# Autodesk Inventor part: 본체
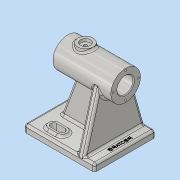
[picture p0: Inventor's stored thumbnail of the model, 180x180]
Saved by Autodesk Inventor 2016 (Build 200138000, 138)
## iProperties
Created: 2019-10
Part Number: 본체
Material: 알루미늄 6061
Document SubType Name: Modeling
Designer: MIRAE
Density: 2.7 g/cm^3
Appearance: 알루미늄 - 평지
Mass: 584.809 g
Surface Area: 539.314 cm^2
Volume: 216.596 cm^3
Author: MIRAE
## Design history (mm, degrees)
sketch "스케치1"
  geometry: L1 (-41, 0)-(41, 0); L2 (-41, 0)-(-41, 21); L3 (-41, 21)-(41, 21); L4 (41, 21)-(41, 0); 2 further points
  constraints: 8 end point, 2 midpoint, 2 perpendicular, 1 horizontal, 1 vertical, 1 vertical alignment
  dimensions: "d0" = 42 diameter of L3 L1; "d1" = 82 distance between parallel lines of L4 L2
revolve "회전1" sketch "스케치1" stored, may be unused: angle "d2" = 90 deg
sketch "스케치2"
  geometry: L1 (41, 21)-(41, -21) reference; L2 (41, 0)-(-41, 0); L3 (-41, 21)-(-41, -21) reference; L4 (41, 0)-(41, 14.5); L5 (41, 14.5)-(-21, 14.5); L6 (-21, 14.5)-(-21, 11.5); L7 (-21, 11.5)-(-41, 11.5); L8 (-41, 11.5)-(-41, 0); 1 further point
  constraints: 12 end point, 2 midpoint, 2 perpendicular, 2 point on line, 1 collinear, 1 horizontal
  dimensions: "d3" = 29 diameter of L5 L2; "d4" = 23 diameter of L7 L2; "d5" = 62 distance of L4.end L5.end
revolve "회전2" sketch "스케치2" stored, may be unused: angle "d6" = 90 deg
node "작업 평면1"
sketch "스케치3"
  geometry: L1 (-60, 43)-(40, 43); L2 (40, 43)-(40, -43); L3 (40, -43)-(-60, -43); L4 (-60, -43)-(-60, 43); 2 further points
  constraints: 8 end point, 2 parallel, 1 horizontal, 1 horizontal alignment, 1 midpoint, 1 perpendicular
  dimensions: "d87" = 100 distance of L2.end L3.end; "d88" = 86 distance of L1.end L2.end; "d89" = 40 distance from line of L2 point (0, 0)
extrude "돌출1" join sketch "스케치3" distance "d10" = 10; taper "d11" = 0 deg
node "작업 평면2"
node "작업 평면3"
sketch "스케치7"
  geometry: L1 (-41, -21)-(-41, 21) reference; C1 r 11 at (-16, 0); 1 further point
  constraints: 1 centre point, 1 horizontal alignment
  dimensions: "d24" = 22 diameter of C1; "d25" = 25 distance from line of L1 C1.centre
extrude "돌출3" join sketch "스케치7" stored distance "d26" = 10; taper "d27" = 0 deg
sketch "스케치8"
  geometry: L1 (-34, 27)-(-22, 27); L2 (-34, 20)-(-22, 20); L3 (-22, 34)-(-34, 34); L4 (-60, 43)-(-60, -43) reference; A1 r 7 centre (-34, 27) between (-34, 34) and (-34, 20); A2 r 7 centre (-22, 27) between (-22, 20) and (-22, 34); 2 further points
  constraints: 8 end point, 4 point on circle, 4 tangent, 2 centre point, 1 horizontal, 1 midpoint, 1 parallel
  dimensions: "d28" = 12 distance of L1.start L1.end; "d31" = 14 distance between parallel lines of L2 L3; "d32" = 27 vertical distance of point (0, 0) L1.end; "d90" = 26 distance from line of L4 L1.start
extrude "돌출4" join sketch "스케치8" distance "d33" = 3; taper "d34" = 0 deg
sketch "스케치9"
  geometry: L1 (-34, 27)-(-22, 27); L2 (-34, 22.5)-(-22, 22.5); L3 (-22, 31.5)-(-34, 31.5); A1 r 4.5 centre (-34, 27) between (-34, 31.5) and (-34, 22.5); A2 r 4.5 centre (-22, 27) between (-22, 22.5) and (-22, 31.5); A3 r 7 centre (-22, 27) between (-22, 20) and (-22, 34) reference; 2 further points
  constraints: 8 end point, 4 point on circle, 4 tangent, 2 centre point, 1 concentric, 1 horizontal, 1 midpoint, 1 parallel
  dimensions: "d35" = 9 distance between parallel lines of L2 L3; "d36" = 12 distance of L1.start L1.end
extrude "돌출5" cut sketch "스케치9" stored distance "d37" = 3; taper "d38" = 0 deg
hole "구멍1" diameter "d41" = 4.917; stored, may be unused: countersink angle "d45" = 90 deg, drill point angle "d47" = 118 deg; dims "d39" = 10, "d40" = 10, "d42" = 12, "d43" = 14, "d44" = 4, "d46" = 17.1
sketch "스케치10"
  geometry: 2 further points
  constraints: 1 horizontal alignment
  dimensions: "d48" = 18 distance of point (0, 0) point (-18, 0)
hole "구멍2" sketch "스케치10" at (-18, 0) diameter "d49" = 2.459; stored, may be unused: countersink angle "d53" = 90 deg, drill point angle "d55" = 118 deg; dims "d50" = 8, "d51" = 14, "d52" = 4, "d54" = 10
node "작업 평면4"
fillet "모깎기4" dims "d77" = 3
chamfer "모따기1" distance "d78" = 1; stored, may be unused: second distance "d79" = 2, angle "d80" = 45 deg
fillet "모깎기5" dims "d91" = 3
fillet "모깎기6" dims "d92" = 3
node "작업 평면5"
sketch "스케치16"
  geometry: L1 (-42.889, -78.191)-(-21, 0); L2 (-21, 0)-(21, 0); L3 (0, 0)-(0, -86); L4 (-40, -86)-(40, -86) reference; L5 (42.889, -78.191)-(21, 0); A1 r 3 centre (-40, -79) between (-40, -76) and (-43, -79) reference; A2 r 3 centre (40, -79) between (43, -79) and (40, -76); A3 r 21 centre (0, 0) between (-21, 0) and (21, 0); 1 further point
  constraints: 8 end point, 6 point on circle, 5 symmetric about line, 2 centre point, 2 midpoint, 1 coincident, 1 horizontal, 1 horizontal alignment, 1 tangent, 2 other
feature "리브4" sketch "스케치16" dims "d94" = 1, "d95" = 10, "d96" = 0, "d97" = 0, "d98" = 1, "d99" = 1
sketch "스케치17"
  geometry: L1 (45, -76)-(33.492, -44.381); L2 (60, -86)-(60, -79) reference; L3 (57, -76)-(-15, -76) reference; 1 further point
  constraints: 2 end point, 1 point on line
  dimensions: "d100" = 15 distance from line of L2 L1.start; "d101" = 70 deg angle of L3 L1
feature "리브5" sketch "스케치17" dims "d102" = 1, "d103" = 10, "d104" = 0, "d105" = 0, "d106" = 1, "d107" = 1
fillet "모깎기7" dims "d108" = 3
fillet "모깎기8" dims "d109" = 3
sketch "스케치18"
  geometry: L1 (-57, -43)-(37, -43) reference; L2 (40, -40)-(40, 40) reference; 2 further points
  constraints: 1 other
  dimensions: "d110" = 43 distance from line of L1 point (33, 0); "d111" = 7 distance from line of L2 point (33, 0)
feature "엠보싱2" sketch "스케치18" dims "d0" = 42, "d1" = 82, "d10" = 10, "d11" = 0, "d112" = 0.5, "d113" = 0
feature "분할1"
node "솔리드1"
mirror "대칭1"
pattern_circular "원형 패턴1" dims angle "d57" = 360 deg
mirror "대칭2"
other parameters: "d7" = -86, "d12" = 25, "d23" = 24, "d93" = 25
